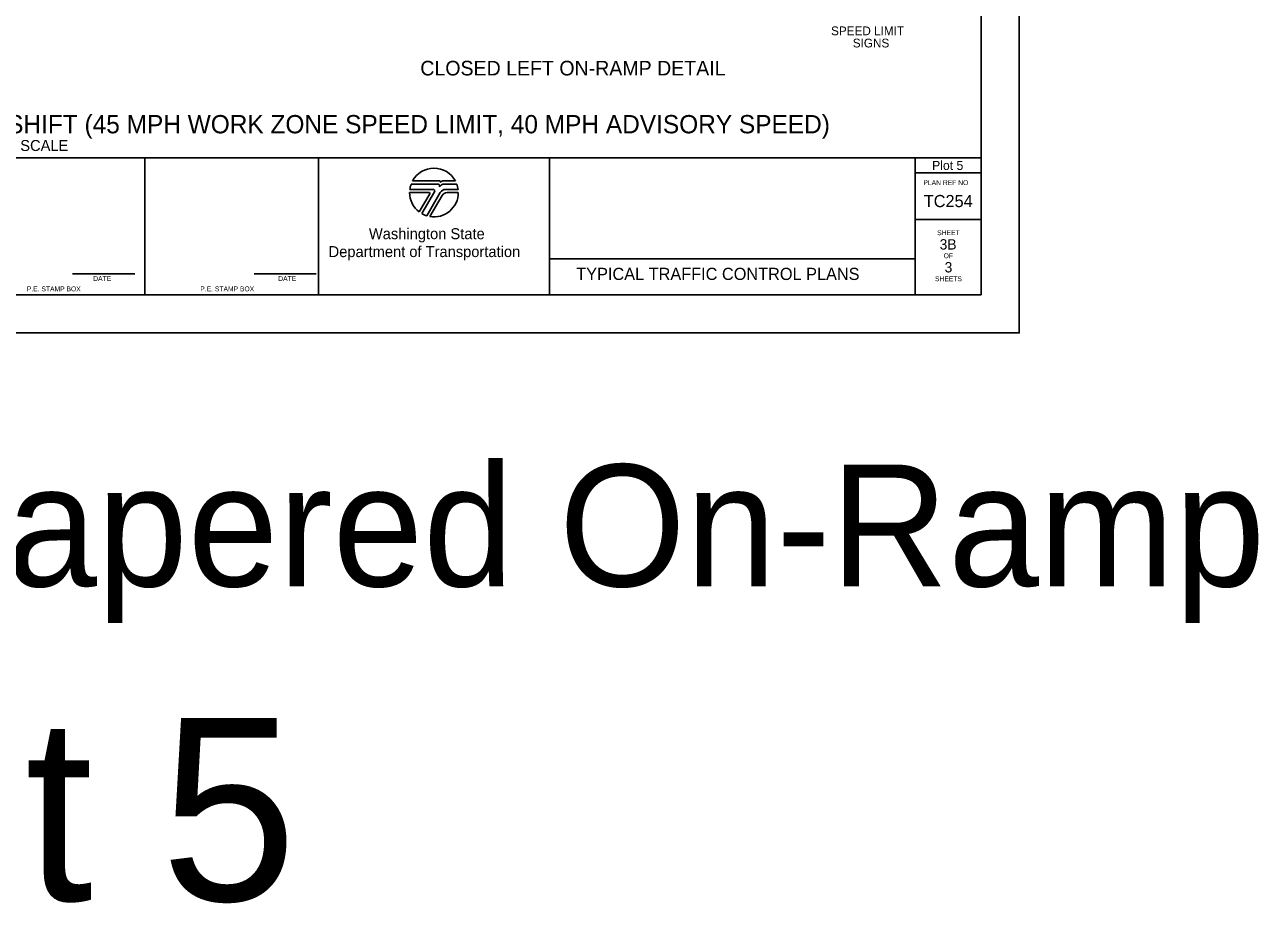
# Model space of a CAD drawing. Extents: x 99999 to 100116, y 99995 to 100013.
# Drawn here: x 100087.9 to 100098.02, y 99995.01 to 100002.22 of the extents above; entities that cross this region are included whole.
import ezdxf

# ---------------------------------------------------------------- set-up
doc = ezdxf.new("R2010")
doc.units = 0
for name, color, linetype in [('SH_DE_DetailHeading1Text', 7, 'Continuous'), ('SH_DE_DetailHeading2Text', 7, 'Continuous'), ('SH_GI_PlotLimits', 7, 'Continuous'), ('SH_GI_SheetBorder', 7, 'Continuous'), ('SH_GI_SheetLocationText', 7, 'Continuous'), ('SH_GI_SheetTextInCells', 7, 'Continuous'), ('SH_GI_TitleBlockText', 7, 'Continuous'), ('SH_GI_WSDOTLogo', 7, 'Continuous'), ('TR_SN_ConstructionSigns', 7, 'Continuous')]:
    doc.layers.add(name, color=color, linetype=linetype)

msp = doc.modelspace()

# ---------------------------------------------------------------- linework, layer by layer
at = {"layer": 'SH_GI_PlotLimits'}
msp.add_lwpolyline([(100079.062, 99999.687), (100096.062, 99999.687), (100096.062, 100010.687), (100079.062, 100010.687)], close=True, dxfattribs=at)
at = {"layer": 'SH_GI_SheetBorder'}
for p, q in [((100095.75, 100010.375), (100095.75, 100000)), ((100080, 100001.126), (100095.75, 100001.126)), ((100088.883, 100000), (100088.883, 100001.126)), ((100090.309, 100001.126), (100090.309, 100000)), ((100092.205, 100001.126), (100092.205, 100000)), ((100095.208, 100001.126), (100095.208, 100000)), ((100095.208, 100001.001), (100095.75, 100001.001)), ((100095.208, 100000.618), (100095.75, 100000.618)), ((100092.205, 100000.295), (100095.208, 100000.295)), ((100088.29, 100000.173), (100088.802, 100000.173)), ((100089.78, 100000.173), (100090.291, 100000.173)), ((100080, 100000), (100095.75, 100000))]:
    msp.add_line(p, q, dxfattribs=at)
at = {"layer": 'SH_GI_WSDOTLogo'}
for p, q in [((100091.059, 100000.866), (100091.25, 100000.866)), ((100091.289, 100000.909), (100091.07, 100000.909)), ((100091.303, 100000.935), (100091.081, 100000.935)), ((100091.433, 100000.935), (100091.335, 100000.935)), ((100091.445, 100000.909), (100091.343, 100000.909)), ((100091.343, 100000.909), (100091.343, 100000.909)), ((100091.356, 100000.866), (100091.456, 100000.866)), ((100091.057, 100000.84), (100091.215, 100000.84)), ((100091.222, 100000.828), (100091.136, 100000.681)), ((100091.261, 100000.846), (100091.157, 100000.667)), ((100091.199, 100000.649), (100091.309, 100000.839)), ((100091.224, 100000.643), (100091.324, 100000.816)), ((100091.365, 100000.839), (100091.457, 100000.839))]:
    msp.add_line(p, q, dxfattribs=at)
for centre, radius, start, end in [((100091.257, 100000.84), 0.2, 28.4787, 151.532), ((100091.257, 100000.84), 0.2, 159.696, 172.5057), ((100091.25, 100000.853), 0.0131, 329.7683, 90), ((100091.289, 100000.895), 0.0148, 327.8418, 89.9985), ((100091.343, 100000.861), 0.0484, 89.9953, 147.8238), ((100091.303, 100000.926), 0.00903, 329.8742, 90.0033), ((100091.356, 100000.812), 0.0542, 90, 149.9974), ((100091.335, 100000.907), 0.0287, 90.0072, 148.1676), ((100091.257, 100000.84), 0.2, 7.4943, 20.2941), ((100091.257, 100000.84), 0.2, 179.9986, 232.8433), ((100091.215, 100000.832), 0.0082, 329.7436, 90), ((100091.257, 100000.84), 0.2, 260.5455, 359.8086), ((100091.365, 100000.792), 0.0476, 90, 150.0543), ((100091.257, 100000.84), 0.2, 239.7929, 253.0448)]:
    msp.add_arc(centre, radius, start, end, dxfattribs=at)

# ---------------------------------------------------------------- texts
at = {"layer": 'SH_DE_DetailHeading1Text'}
for s, height, p in [("FREEWAY (2 LANES): SINGLE LEFT LANE CLOSURE, 9' MAX RIGHT SHOULDER SHIFT (45 MPH WORK ZONE SPEED LIMIT, 40 MPH ADVISORY SPEED)", 0.15, (100080.091, 100001.326)), ('NOT TO SCALE', 0.09, (100087.373, 100001.181))]:
    msp.add_text(s, height=height, rotation=360, dxfattribs=at).set_placement(p)
at = {"layer": 'SH_DE_DetailHeading2Text'}
msp.add_text('CLOSED LEFT ON-RAMP DETAIL', height=0.12, rotation=360, dxfattribs=at).set_placement((100091.145, 100001.801))
at = {"layer": 'SH_GI_SheetBorder'}
msp.add_text('PLAN REF NO', height=0.04003, dxfattribs=at).set_placement((100095.275, 100000.901))
at = {"layer": 'SH_GI_SheetLocationText'}
for s, height, p in [('Plot 5', 0.075, (100095.346, 100001.025)), ('Left Ramps: Tapered On-Ramp', 1, (100079.351, 99997.607)), ('Plot 5', 1.5, (100085.001, 99995.027))]:
    msp.add_text(s, height=height, dxfattribs=at).set_placement(p)
at = {"layer": 'SH_GI_SheetTextInCells'}
for s, height, p in [('Washington State', 0.09007, (100090.723, 100000.457)), ('SHEET', 0.04, (100095.388, 100000.49)), ('Department of Transportation', 0.09007, (100090.392, 100000.31)), ('OF', 0.04, (100095.441, 100000.301)), ('DATE', 0.04, (100088.46, 100000.114)), ('DATE', 0.04, (100089.979, 100000.114)), ('SHEETS', 0.04, (100095.37, 100000.112)), ('P.E. STAMP BOX', 0.04003, (100087.915, 100000.029)), ('P.E. STAMP BOX', 0.04003, (100089.339, 100000.029))]:
    msp.add_text(s, height=height, dxfattribs=at).set_placement(p)
at = {"layer": 'SH_GI_TitleBlockText'}
for s, height, p in [('TC254', 0.1, (100095.278, 100000.72)), ('3B', 0.085, (100095.408, 100000.372)), ('3', 0.085, (100095.449, 100000.184)), ('TYPICAL TRAFFIC CONTROL PLANS', 0.1, (100092.425, 100000.122))]:
    msp.add_text(s, height=height, dxfattribs=at).set_placement(p)
at = {"layer": 'TR_SN_ConstructionSigns'}
for s, p in [('SPEED LIMIT', (100094.517, 100002.131)), ('SIGNS', (100094.695, 100002.031))]:
    msp.add_text(s, height=0.072, dxfattribs=at).set_placement(p)

doc.saveas('drawing.dxf')
